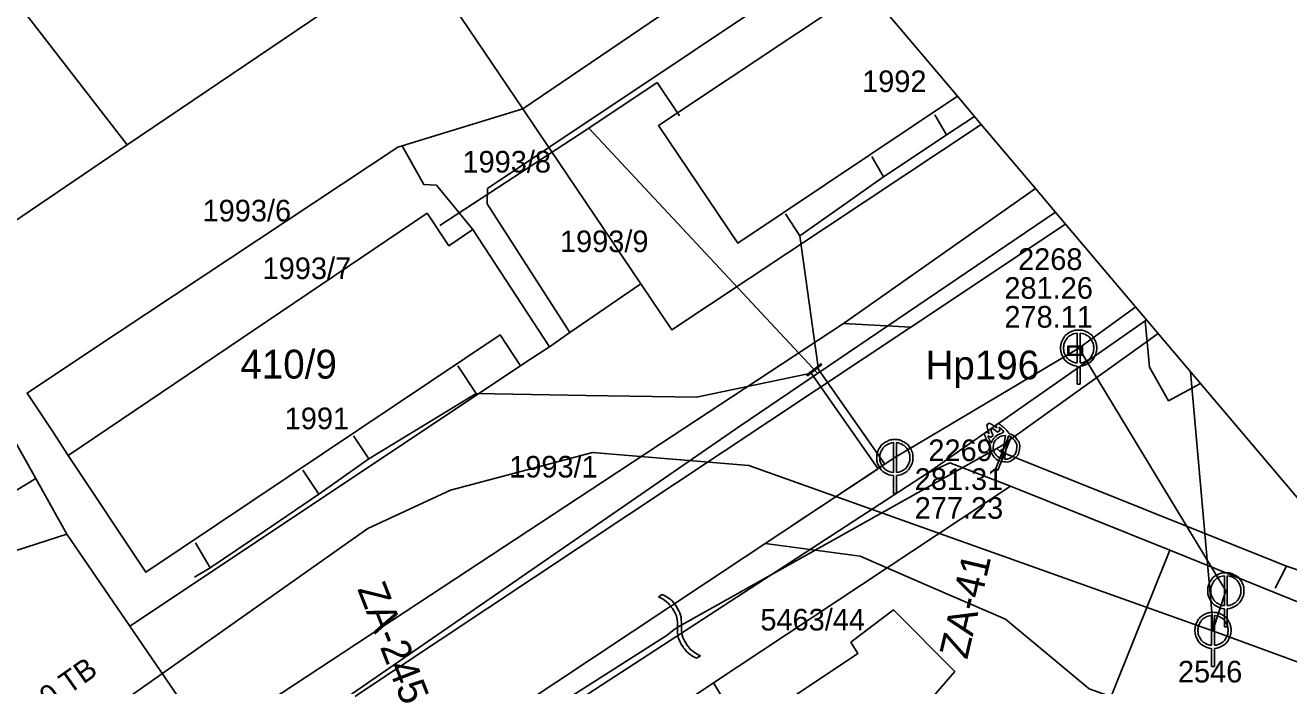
# Model space of a CAD drawing. Extents: x -570698 to -570232, y -1086952 to -1086596.
# Drawn here: x -570363.7 to -570276.2, y -1086720.9 to -1086675.1 of the extents above; entities that cross this region are included whole.
import ezdxf

# ---------------------------------------------------------------- set-up
doc = ezdxf.new("R2010")
doc.units = 0
for name, color, linetype in [('Adresní místo-text', 7, 'Continuous'), ('Armatura - popis', 7, 'Continuous'), ('Armatura vodovodní', 7, 'Continuous'), ('Chránička - kanalizace', 7, 'Continuous'), ('Default', 7, 'Continuous'), ('Hydrant', 7, 'Continuous'), ('Kanalizační komora-vzt.bod', 7, 'Continuous'), ('Kanalizační přípojka', 7, 'Continuous'), ('Kanalizační stoka', 7, 'Continuous'), ('Kanalizační šachta', 7, 'Continuous'), ('Označení hydrantu', 7, 'Continuous'), ('Parcela-polygon', 7, 'Continuous'), ('Parcela-text', 7, 'Continuous'), ('Popis kmenové stoky', 7, 'Continuous'), ('Popis šachty', 7, 'Continuous'), ('Vodovodní přípojka', 7, 'Continuous'), ('Vodovodní řad', 7, 'Continuous'), ('Změna stáří vedení', 7, 'Continuous')]:
    doc.layers.add(name, color=color, linetype=linetype)

msp = doc.modelspace()

# ---------------------------------------------------------------- linework, layer by layer
at = {"layer": 'Armatura vodovodní'}
for points in [[(-570308.538, -1086698.638), (-570309.517, -1086699.415), (-570309.566, -1086699.354), (-570308.587, -1086698.577), (-570308.538, -1086698.638)], [(-570295.414, -1086703.638), (-570296.34, -1086705.96), (-570296.485, -1086705.902), (-570295.559, -1086703.58), (-570295.414, -1086703.638)]]:
    msp.add_lwpolyline(points, dxfattribs=at)
at = {"layer": 'Chránička - kanalizace'}
msp.add_lwpolyline([(-570304.699, -1086705.905), (-570310.512, -1086709.76)], dxfattribs=at)
at = {"layer": 'Default'}
for points, degree in [([(-570290.833, -1086698.738), (-570291.091, -1086698.72), (-570291.353, -1086698.574), (-570291.65, -1086698.41), (-570291.815, -1086698.113), (-570291.98, -1086697.815), (-570291.98, -1086697.49), (-570291.98, -1086697.163), (-570291.812, -1086696.863), (-570291.643, -1086696.562), (-570291.345, -1086696.401), (-570291.047, -1086696.24), (-570290.73, -1086696.24), (-570290.415, -1086696.24), (-570290.116, -1086696.401), (-570289.817, -1086696.562), (-570289.648, -1086696.863), (-570289.48, -1086697.163), (-570289.48, -1086697.49), (-570289.48, -1086697.815), (-570289.645, -1086698.113), (-570289.81, -1086698.41), (-570290.107, -1086698.574), (-570290.369, -1086698.72), (-570290.627, -1086698.738)], 3), ([(-570290.833, -1086696.452), (-570291.03, -1086696.469), (-570291.245, -1086696.584), (-570291.494, -1086696.719), (-570291.633, -1086696.969), (-570291.772, -1086697.219), (-570291.772, -1086697.49), (-570291.772, -1086697.761), (-570291.636, -1086698.008), (-570291.499, -1086698.254), (-570291.25, -1086698.391), (-570291.038, -1086698.511), (-570290.833, -1086698.525)], 3), ([(-570290.627, -1086698.525), (-570290.422, -1086698.511), (-570290.208, -1086698.391), (-570289.961, -1086698.254), (-570289.824, -1086698.008), (-570289.688, -1086697.761), (-570289.688, -1086697.49), (-570289.688, -1086697.219), (-570289.828, -1086696.969), (-570289.968, -1086696.719), (-570290.217, -1086696.584), (-570290.43, -1086696.469), (-570290.627, -1086696.452)], 3), ([(-570296.93, -1086703.418), (-570297.057, -1086703.119), (-570297.091, -1086702.824)], 2), ([(-570296.925, -1086702.703), (-570296.656, -1086702.824), (-570296.408, -1086703.034)], 2), ([(-570296.3, -1086702.719), (-570296.058, -1086702.874), (-570295.857, -1086703.063)], 2), ([(-570297.075, -1086703.949), (-570297.194, -1086703.703), (-570297.267, -1086703.424)], 2), ([(-570297.037, -1086703.573), (-570296.93, -1086703.836), (-570296.784, -1086704.073)], 2), ([(-570295.537, -1086703.422), (-570295.223, -1086703.514), (-570295.021, -1086703.792), (-570294.777, -1086704.127), (-570294.841, -1086704.535), (-570294.906, -1086704.944), (-570295.242, -1086705.189), (-570295.575, -1086705.432), (-570295.983, -1086705.369), (-570296.392, -1086705.305), (-570296.636, -1086704.971), (-570296.841, -1086704.69), (-570296.832, -1086704.362)], 3), ([(-570296.361, -1086703.334), (-570296.577, -1086703.107), (-570296.857, -1086702.968), (-570296.812, -1086703.276), (-570296.661, -1086703.553)], 3), ([(-570296.784, -1086704.073), (-570296.706, -1086703.813), (-570296.491, -1086703.629)], 2), ([(-570295.798, -1086703.566), (-570296.076, -1086703.552), (-570296.311, -1086703.723), (-570296.584, -1086703.922), (-570296.636, -1086704.254), (-570296.688, -1086704.586), (-570296.489, -1086704.858), (-570296.317, -1086705.094), (-570296.047, -1086705.165)], 3), ([(-570296.343, -1086703.521), (-570296.102, -1086703.374), (-570295.828, -1086703.378), (-570296.01, -1086703.165), (-570296.229, -1086702.984)], 3), ([(-570295.862, -1086705.194), (-570295.587, -1086705.206), (-570295.353, -1086705.036), (-570295.082, -1086704.838), (-570295.03, -1086704.506), (-570294.977, -1086704.174), (-570295.176, -1086703.901), (-570295.347, -1086703.667), (-570295.612, -1086703.595)], 3), ([(-570295.634, -1086703.304), (-570295.618, -1086703.321), (-570295.537, -1086703.422)], 2), ([(-570303.573, -1086706.338), (-570303.831, -1086706.32), (-570304.093, -1086706.174), (-570304.39, -1086706.01), (-570304.555, -1086705.713), (-570304.72, -1086705.415), (-570304.72, -1086705.09), (-570304.72, -1086704.763), (-570304.552, -1086704.463), (-570304.383, -1086704.162), (-570304.085, -1086704.001), (-570303.787, -1086703.84), (-570303.47, -1086703.84), (-570303.155, -1086703.84), (-570302.856, -1086704.001), (-570302.557, -1086704.162), (-570302.388, -1086704.463), (-570302.22, -1086704.763), (-570302.22, -1086705.09), (-570302.22, -1086705.415), (-570302.385, -1086705.713), (-570302.55, -1086706.01), (-570302.847, -1086706.174), (-570303.109, -1086706.32), (-570303.367, -1086706.338)], 3), ([(-570303.573, -1086704.052), (-570303.77, -1086704.069), (-570303.985, -1086704.184), (-570304.234, -1086704.319), (-570304.373, -1086704.569), (-570304.512, -1086704.819), (-570304.512, -1086705.09), (-570304.512, -1086705.361), (-570304.376, -1086705.608), (-570304.239, -1086705.854), (-570303.99, -1086705.991), (-570303.778, -1086706.111), (-570303.573, -1086706.125)], 3), ([(-570303.367, -1086706.125), (-570303.162, -1086706.111), (-570302.948, -1086705.991), (-570302.701, -1086705.854), (-570302.564, -1086705.608), (-570302.428, -1086705.361), (-570302.428, -1086705.09), (-570302.428, -1086704.819), (-570302.568, -1086704.569), (-570302.708, -1086704.319), (-570302.957, -1086704.184), (-570303.17, -1086704.069), (-570303.367, -1086704.052)], 3), ([(-570296.84, -1086704.404), (-570296.838, -1086704.38), (-570296.835, -1086704.357), (-570296.923, -1086704.223), (-570296.982, -1086704.13)], 3), ([(-570280.633, -1086715.568), (-570280.891, -1086715.55), (-570281.153, -1086715.404), (-570281.45, -1086715.24), (-570281.615, -1086714.943), (-570281.78, -1086714.645), (-570281.78, -1086714.32), (-570281.78, -1086713.993), (-570281.612, -1086713.693), (-570281.443, -1086713.392), (-570281.145, -1086713.231), (-570280.847, -1086713.07), (-570280.53, -1086713.07), (-570280.215, -1086713.07), (-570279.916, -1086713.231), (-570279.617, -1086713.392), (-570279.448, -1086713.693), (-570279.28, -1086713.993), (-570279.28, -1086714.32), (-570279.28, -1086714.645), (-570279.445, -1086714.943), (-570279.61, -1086715.24), (-570279.907, -1086715.404), (-570280.169, -1086715.55), (-570280.427, -1086715.568)], 3), ([(-570280.633, -1086713.282), (-570280.83, -1086713.299), (-570281.045, -1086713.414), (-570281.294, -1086713.549), (-570281.433, -1086713.799), (-570281.572, -1086714.049), (-570281.572, -1086714.32), (-570281.572, -1086714.591), (-570281.436, -1086714.838), (-570281.299, -1086715.084), (-570281.05, -1086715.221), (-570280.838, -1086715.341), (-570280.633, -1086715.355)], 3), ([(-570280.427, -1086715.355), (-570280.222, -1086715.341), (-570280.008, -1086715.221), (-570279.761, -1086715.084), (-570279.624, -1086714.838), (-570279.488, -1086714.591), (-570279.488, -1086714.32), (-570279.488, -1086714.049), (-570279.628, -1086713.799), (-570279.768, -1086713.549), (-570280.017, -1086713.414), (-570280.23, -1086713.299), (-570280.427, -1086713.282)], 3), ([(-570317.213, -1086718.996), (-570317.873, -1086718.673), (-570318.203, -1086718.142), (-570318.533, -1086717.612), (-570318.533, -1086716.872), (-570318.53, -1086716.138), (-570318.86, -1086715.607), (-570319.19, -1086715.076), (-570319.853, -1086714.749)], 3), ([(-570319.587, -1086714.584), (-570318.924, -1086714.911), (-570318.594, -1086715.442), (-570318.264, -1086715.973), (-570318.266, -1086716.71), (-570318.268, -1086717.447), (-570317.939, -1086717.975), (-570317.609, -1086718.506), (-570316.947, -1086718.831)], 3), ([(-570281.523, -1086718.318), (-570281.781, -1086718.3), (-570282.043, -1086718.154), (-570282.34, -1086717.99), (-570282.505, -1086717.693), (-570282.67, -1086717.395), (-570282.67, -1086717.07), (-570282.67, -1086716.743), (-570282.502, -1086716.443), (-570282.333, -1086716.142), (-570282.035, -1086715.981), (-570281.737, -1086715.82), (-570281.42, -1086715.82), (-570281.105, -1086715.82), (-570280.806, -1086715.981), (-570280.507, -1086716.142), (-570280.338, -1086716.443), (-570280.17, -1086716.743), (-570280.17, -1086717.07), (-570280.17, -1086717.395), (-570280.335, -1086717.693), (-570280.5, -1086717.99), (-570280.797, -1086718.154), (-570281.059, -1086718.3), (-570281.317, -1086718.318)], 3), ([(-570281.523, -1086716.032), (-570281.72, -1086716.049), (-570281.935, -1086716.164), (-570282.184, -1086716.299), (-570282.323, -1086716.549), (-570282.462, -1086716.799), (-570282.462, -1086717.07), (-570282.462, -1086717.341), (-570282.326, -1086717.588), (-570282.189, -1086717.834), (-570281.94, -1086717.971), (-570281.728, -1086718.091), (-570281.523, -1086718.105)], 3), ([(-570281.317, -1086718.105), (-570281.112, -1086718.091), (-570280.898, -1086717.971), (-570280.651, -1086717.834), (-570280.514, -1086717.588), (-570280.378, -1086717.341), (-570280.378, -1086717.07), (-570280.378, -1086716.799), (-570280.518, -1086716.549), (-570280.658, -1086716.299), (-570280.907, -1086716.164), (-570281.12, -1086716.049), (-570281.317, -1086716.032)], 3)]:
    msp.add_open_spline(points, degree=degree, dxfattribs=at)
at = {"layer": 'Hydrant'}
for points in [[(-570297.091, -1086702.824), (-570296.925, -1086702.703)], [(-570296.408, -1086703.034), (-570296.461, -1086702.836), (-570296.3, -1086702.719)], [(-570297.267, -1086703.424), (-570297.108, -1086703.308), (-570296.93, -1086703.418)], [(-570296.661, -1086703.553), (-570296.822, -1086703.67), (-570297.037, -1086703.573)], [(-570296.491, -1086703.629), (-570296.343, -1086703.521)], [(-570296.229, -1086702.984), (-570296.2, -1086703.216), (-570296.361, -1086703.334)], [(-570296.047, -1086705.165), (-570295.798, -1086703.566)], [(-570295.612, -1086703.595), (-570295.862, -1086705.194)], [(-570295.857, -1086703.063), (-570295.712, -1086703.209), (-570295.634, -1086703.304)], [(-570296.982, -1086704.13), (-570297.075, -1086703.949)], [(-570296.832, -1086704.362), (-570296.84, -1086704.404)]]:
    msp.add_lwpolyline(points, dxfattribs=at)
at = {"layer": 'Kanalizační komora-vzt.bod'}
for points in [[(-570291.472, -1086697.993), (-570291.472, -1086697.35), (-570290.472, -1086697.35), (-570290.472, -1086697.993), (-570291.472, -1086697.993)], [(-570290.535, -1086697.931), (-570290.535, -1086697.412), (-570291.409, -1086697.412), (-570291.409, -1086697.931), (-570290.535, -1086697.931)]]:
    msp.add_lwpolyline(points, dxfattribs=at)
at = {"layer": 'Kanalizační přípojka'}
for points in [[(-570297.944, -1086681.436), (-570299.88, -1086682.71), (-570302.07, -1086684.165), (-570304.26, -1086685.62), (-570307.16, -1086687.67), (-570310.06, -1086689.72), (-570309.41, -1086694.35), (-570308.76, -1086698.98)], [(-570300.71, -1086681.32), (-570299.88, -1086682.71)], [(-570305.07, -1086684.2), (-570304.26, -1086685.62)], [(-570311.04, -1086688.18), (-570310.06, -1086689.72)], [(-570352.02, -1086713.37), (-570350.93, -1086712.74), (-570347.165, -1086710.185), (-570343.4, -1086707.63), (-570341.67, -1086706.4), (-570339.94, -1086705.17), (-570336.22, -1086702.91), (-570332.5, -1086700.65), (-570324.855, -1086700.775), (-570317.21, -1086700.9), (-570313.245, -1086700.07), (-570309.28, -1086699.24)], [(-570333.76, -1086698.72), (-570332.5, -1086700.65)], [(-570309.28, -1086699.24), (-570304.63, -1086705.859)], [(-570308.76, -1086698.98), (-570304.162, -1086705.549)], [(-570340.98, -1086703.58), (-570339.94, -1086705.17)], [(-570344.5, -1086705.95), (-570343.4, -1086707.63)], [(-570351.94, -1086710.99), (-570350.93, -1086712.74)], [(-570305.88, -1086711.93), (-570312.462, -1086711.054)], [(-570272.31, -1086727.54), (-570278.23, -1086725.35), (-570284.12, -1086723.235), (-570290.01, -1086721.12), (-570292.905, -1086718.705), (-570295.8, -1086716.29), (-570300.84, -1086714.11), (-570305.88, -1086711.93)]]:
    msp.add_lwpolyline(points, dxfattribs=at)
at = {"layer": 'Kanalizační stoka'}
msp.add_line((-570282.969, -1086699.146), (-570281.39, -1086717.12), dxfattribs=at)
for points in [[(-570286.778, -1086694.643), (-570290.73, -1086697.49)], [(-570290.73, -1086697.49), (-570303.47, -1086705.09)], [(-570290.73, -1086697.49), (-570280.53, -1086714.32)], [(-570416.01, -1086763.66), (-570340, -1086709.998), (-570334.265, -1086707.341), (-570324.416, -1086704.737), (-570313.599, -1086705.638), (-570281.39, -1086717.12)], [(-570303.47, -1086705.09), (-570334.74, -1086725.83)], [(-570280.53, -1086714.32), (-570281.42, -1086717.07)], [(-570281.39, -1086717.12), (-570261.653, -1086724.356)]]:
    msp.add_lwpolyline(points, dxfattribs=at)
at = {"layer": 'Kanalizační šachta'}
for points in [[(-570290.833, -1086698.525), (-570290.833, -1086696.452)], [(-570290.627, -1086696.452), (-570290.627, -1086698.525)], [(-570290.627, -1086698.738), (-570290.627, -1086699.99), (-570290.833, -1086699.99), (-570290.833, -1086698.738)], [(-570303.573, -1086706.125), (-570303.573, -1086704.052)], [(-570303.367, -1086704.052), (-570303.367, -1086706.125)], [(-570303.367, -1086706.338), (-570303.367, -1086707.59), (-570303.573, -1086707.59), (-570303.573, -1086706.338)], [(-570280.633, -1086715.355), (-570280.633, -1086713.282)], [(-570280.427, -1086713.282), (-570280.427, -1086715.355)], [(-570280.427, -1086715.568), (-570280.427, -1086716.82), (-570280.633, -1086716.82), (-570280.633, -1086715.568)], [(-570281.523, -1086718.105), (-570281.523, -1086716.032)], [(-570281.317, -1086716.032), (-570281.317, -1086718.105)], [(-570281.317, -1086718.318), (-570281.317, -1086719.57), (-570281.523, -1086719.57), (-570281.523, -1086718.318)]]:
    msp.add_lwpolyline(points, dxfattribs=at)
at = {"layer": 'Parcela-polygon'}
for p, q in [((-570299.138, -1086680.025), (-570305.513, -1086672.486)), ((-570297.479, -1086681.987), (-570299.138, -1086680.025)), ((-570293.731, -1086686.419), (-570297.479, -1086681.987)), ((-570291.64, -1086688.892), (-570293.731, -1086686.419)), ((-570286.027, -1086695.53), (-570291.64, -1086688.892)), ((-570282.287, -1086699.954), (-570286.027, -1086695.53)), ((-570266.341, -1086718.811), (-570282.287, -1086699.954))]:
    msp.add_line(p, q, dxfattribs=at)
for points in [[(-570424.7, -1086660.31), (-570395.64, -1086696.83), (-570379.95, -1086716.54), (-570360.86, -1086710.41), (-570363.02, -1086706.55), (-570376.81, -1086714.9), (-570404.01, -1086679.1), (-570376.49, -1086657.78), (-570356.68, -1086683.4), (-570336.7, -1086669.87)], [(-570318.256, -1086657.415), (-570332.91, -1086667.31), (-570336.7, -1086669.87), (-570329.26, -1086680.9), (-570309.653, -1086667.589)], [(-570309.653, -1086667.589), (-570329.26, -1086680.9), (-570327.45, -1086683.58), (-570307.454, -1086670.19)], [(-570307.454, -1086670.19), (-570327.45, -1086683.58), (-570321.07, -1086693.03), (-570318.92, -1086696.23), (-570297.479, -1086681.987)], [(-570305.513, -1086672.486), (-570319.86, -1086682.06), (-570314.36, -1086690.21), (-570299.138, -1086680.025)], [(-570299.138, -1086680.025), (-570314.36, -1086690.21), (-570319.86, -1086682.06), (-570305.513, -1086672.486)], [(-570297.479, -1086681.987), (-570318.92, -1086696.23), (-570321.07, -1086693.03), (-570325.99, -1086696.42), (-570327.4, -1086697.4), (-570329.04, -1086698.47), (-570329.42, -1086698.72), (-570356.5, -1086716.77), (-570351.03, -1086724.75), (-570323.72, -1086706.78), (-570320.65, -1086704.75), (-570307.04, -1086695.8), (-570293.731, -1086686.419)], [(-570293.731, -1086686.419), (-570307.04, -1086695.8), (-570302.37, -1086696.04), (-570291.64, -1086688.892)], [(-570291.64, -1086688.892), (-570302.37, -1086696.04), (-570396.95, -1086758.9), (-570417.85, -1086767.9), (-570426.99, -1086775.07), (-570430.55, -1086777.63), (-570432.81, -1086779.33), (-570437.1, -1086782.56), (-570450.62, -1086793.64), (-570452.87, -1086797.51), (-570456.3, -1086803.42), (-570469.27, -1086814.47), (-570499.22, -1086840.17), (-570503.94, -1086844.12), (-570508.33, -1086847.72), (-570512.7, -1086850.77), (-570519.4, -1086855.31), (-570522.96, -1086857.62), (-570528.66, -1086861.02), (-570535.32, -1086864.67), (-570544.494, -1086869.551)], [(-570471.26, -1086826.6), (-570461.73, -1086819.28), (-570457.91, -1086816.88), (-570450.83, -1086812.94), (-570436.06, -1086800.74), (-570433.95, -1086798.53), (-570429.07, -1086790.91), (-570420.2, -1086784.42), (-570412, -1086778.75), (-570347.1, -1086736.01), (-570341.15, -1086732.35), (-570332.8, -1086726.72), (-570301.2, -1086706.16), (-570286.13, -1086695.6), (-570286.027, -1086695.53)], [(-570282.287, -1086699.954), (-570284.51, -1086701.15), (-570285.82, -1086698.81), (-570286.13, -1086695.6), (-570301.2, -1086706.16), (-570299.67, -1086705.46), (-570295.46, -1086707.06), (-570284.42, -1086711.51), (-570266.64, -1086718.69), (-570266.341, -1086718.811)], [(-570286.027, -1086695.53), (-570286.13, -1086695.6), (-570285.82, -1086698.81), (-570284.51, -1086701.15), (-570282.287, -1086699.954)], [(-570289.55, -1086724.3), (-570284.42, -1086711.51), (-570295.46, -1086707.06), (-570316.04, -1086720.72), (-570314.04, -1086724.02), (-570306.03, -1086718.67), (-570306.52, -1086717.89), (-570303.57, -1086715.65), (-570299.32, -1086719.92), (-570302.43, -1086723.54)], [(-570250.717, -1086773.479), (-570250.86, -1086773.06), (-570250.95, -1086772.82), (-570253.65, -1086764.94), (-570267.22, -1086725.38), (-570267.25, -1086723.7), (-570266.64, -1086718.69), (-570284.42, -1086711.51), (-570289.55, -1086724.3), (-570275.18, -1086729.09), (-570271.35, -1086730.46), (-570268.66, -1086737.98), (-570264.62, -1086749.76), (-570260.63, -1086761.38), (-570256.55, -1086773.27), (-570255.281, -1086776.983)]]:
    msp.add_lwpolyline(points, dxfattribs=at)
for points in [[(-570363.02, -1086706.55), (-570370.68, -1086692.89), (-570356.68, -1086683.4), (-570376.49, -1086657.78), (-570404.01, -1086679.1), (-570376.81, -1086714.9)], [(-570355.38, -1086713.04), (-570360.77, -1086704.95), (-570361.85, -1086703.26), (-570363.62, -1086700.62), (-570359.23, -1086697.68), (-570337.92, -1086683.56), (-570337.62, -1086683.47), (-570329.26, -1086680.9), (-570336.7, -1086669.87), (-570356.68, -1086683.4), (-570370.68, -1086692.89), (-570363.02, -1086706.55), (-570360.86, -1086710.41), (-570356.5, -1086716.77), (-570329.42, -1086698.72), (-570330.83, -1086696.57)], [(-570327.45, -1086683.58), (-570329.26, -1086680.9), (-570337.62, -1086683.47), (-570336.12, -1086686.15), (-570335.25, -1086686.19), (-570332.71, -1086689.28), (-570327.4, -1086697.4), (-570325.99, -1086696.42), (-570331.73, -1086687.5), (-570331.7, -1086686.43)], [(-570337.62, -1086683.47), (-570337.92, -1086683.56), (-570359.23, -1086697.68), (-570363.62, -1086700.62), (-570361.85, -1086703.26), (-570360.77, -1086704.95), (-570335.89, -1086688.13), (-570334.38, -1086690.4), (-570332.71, -1086689.28), (-570335.25, -1086686.19), (-570336.12, -1086686.15)], [(-570321.07, -1086693.03), (-570327.45, -1086683.58), (-570331.7, -1086686.43), (-570331.73, -1086687.5), (-570325.99, -1086696.42)], [(-570360.77, -1086704.95), (-570355.38, -1086713.04), (-570330.83, -1086696.57), (-570329.42, -1086698.72), (-570329.04, -1086698.47), (-570327.4, -1086697.4), (-570332.71, -1086689.28), (-570334.38, -1086690.4), (-570335.89, -1086688.13)], [(-570396.95, -1086758.9), (-570302.37, -1086696.04), (-570307.04, -1086695.8), (-570320.65, -1086704.75), (-570323.72, -1086706.78), (-570351.03, -1086724.75), (-570396.74, -1086755.3), (-570401.48, -1086758.74), (-570401.33, -1086758.86), (-570399.38, -1086759.31)], [(-570334.23, -1086732.06), (-570329.64, -1086729.03), (-570320.74, -1086723.85), (-570316.04, -1086720.72), (-570295.46, -1086707.06), (-570299.67, -1086705.46), (-570301.2, -1086706.16), (-570332.8, -1086726.72), (-570333.78, -1086727.8), (-570334.21, -1086728.79), (-570334.46, -1086729.98), (-570334.32, -1086731.67)], [(-570351.03, -1086724.75), (-570356.5, -1086716.77), (-570360.86, -1086710.41), (-570379.95, -1086716.54), (-570413.68, -1086729.07), (-570423.89, -1086728.17), (-570416.22, -1086738.58), (-570401.54, -1086756.4), (-570400.84, -1086756.79), (-570396.74, -1086755.3)], [(-570318.21, -1086732.66), (-570318.39, -1086732.43), (-570316.21, -1086731.2), (-570315.45, -1086732.68), (-570310.6, -1086729.67), (-570310.93, -1086729.12), (-570309.31, -1086728.12), (-570308.97, -1086728.66), (-570301.97, -1086724.32), (-570302.43, -1086723.54), (-570299.32, -1086719.92), (-570303.57, -1086715.65), (-570306.52, -1086717.89), (-570306.03, -1086718.67), (-570314.04, -1086724.02), (-570316.04, -1086720.72), (-570320.74, -1086723.85), (-570329.64, -1086729.03), (-570331.17, -1086730.39), (-570331.42, -1086731.27), (-570321.63, -1086734.82), (-570321.41, -1086734.04), (-570320.55, -1086734.44)]]:
    msp.add_lwpolyline(points, close=True, dxfattribs=at)
at = {"layer": 'Vodovodní přípojka'}
for p, q in [((-570324.686, -1086682.236), (-570319.948, -1086679.066)), ((-570318.389, -1086681.391), (-570319.948, -1086679.066)), ((-570324.686, -1086682.236), (-570335.011, -1086689.001)), ((-570276.32, -1086712.62), (-570277.114, -1086714.142))]:
    msp.add_line(p, q, dxfattribs=at)
msp.add_lwpolyline([(-570308.821, -1086699.243), (-570324.686, -1086682.236)], dxfattribs=at)
at = {"layer": 'Vodovodní řad'}
msp.add_line((-570296.2, -1086704.65), (-570295.83, -1086704.38), dxfattribs=at)
for points in [[(-570292.345, -1086688.058), (-570314.222, -1086702.909), (-570395.154, -1086758.795)], [(-570296.069, -1086704.282), (-570285.213, -1086696.493)], [(-570318.4, -1086716.79), (-570296.069, -1086704.282)], [(-570295.95, -1086704.77), (-570296.2, -1086704.65), (-570296.41, -1086704.46)], [(-570269.613, -1086714.942), (-570272.91, -1086713.76), (-570276.32, -1086712.62), (-570295.95, -1086704.77)], [(-570318.4, -1086716.79), (-570318.77, -1086717.02), (-570319.01, -1086717.215), (-570319.25, -1086717.41), (-570326.575, -1086722.065), (-570335.3, -1086727.63), (-570336.1, -1086728.14), (-570336.47, -1086728.37)]]:
    msp.add_lwpolyline(points, dxfattribs=at)
at = {"layer": 'Změna stáří vedení'}
for points in [[(-570319.853, -1086714.749), (-570319.587, -1086714.584)], [(-570316.947, -1086718.831), (-570317.213, -1086718.996)]]:
    msp.add_lwpolyline(points, dxfattribs=at)

# ---------------------------------------------------------------- texts
at = {"layer": 'Adresní místo-text'}
msp.add_text('410/9', height=2, dxfattribs=at).set_placement((-570348.835, -1086699.61))
at = {"layer": 'Armatura - popis'}
for s, rotation, p in [('ZA-41', 76.77703, (-570298.456, -1086719.134)), ('ZA-245', 291.33683, (-570340.744, -1086714.197))]:
    msp.add_text(s, height=2, rotation=rotation, dxfattribs=at).set_placement(p)
at = {"layer": 'Označení hydrantu'}
msp.add_text('Hp196', height=2, dxfattribs=at).set_placement((-570301.348, -1086699.667))
at = {"layer": 'Parcela-text'}
for s, p in [('1992', (-570305.74, -1086679.74)), ('1993/8', (-570333.44, -1086685.32)), ('1993/6', (-570351.45, -1086688.71)), ('1993/9', (-570326.68, -1086690.84)), ('1993/7', (-570347.29, -1086692.71)), ('1991', (-570345.76, -1086703.12)), ('1993/1', (-570330.2, -1086706.47)), ('5463/44', (-570312.79, -1086717.08))]:
    msp.add_text(s, height=1.5, dxfattribs=at).set_placement(p)
at = {"layer": 'Popis kmenové stoky'}
msp.add_text('Obdélníkové 2000/1500 TB', height=1.5, rotation=35.22155, dxfattribs=at).set_placement((-570378.57, -1086734.15))
at = {"layer": 'Popis šachty'}
for s, p in [('2268', (-570294.929, -1086692.075)), ('281.26', (-570295.879, -1086694.075)), ('278.11', (-570295.879, -1086696.075)), ('2269', (-570301.145, -1086705.33)), ('281.31', (-570302.095, -1086707.33)), ('277.23', (-570302.095, -1086709.33)), ('2546', (-570283.85, -1086720.682))]:
    msp.add_text(s, height=1.5, dxfattribs=at).set_placement(p)

doc.saveas('drawing.dxf')
